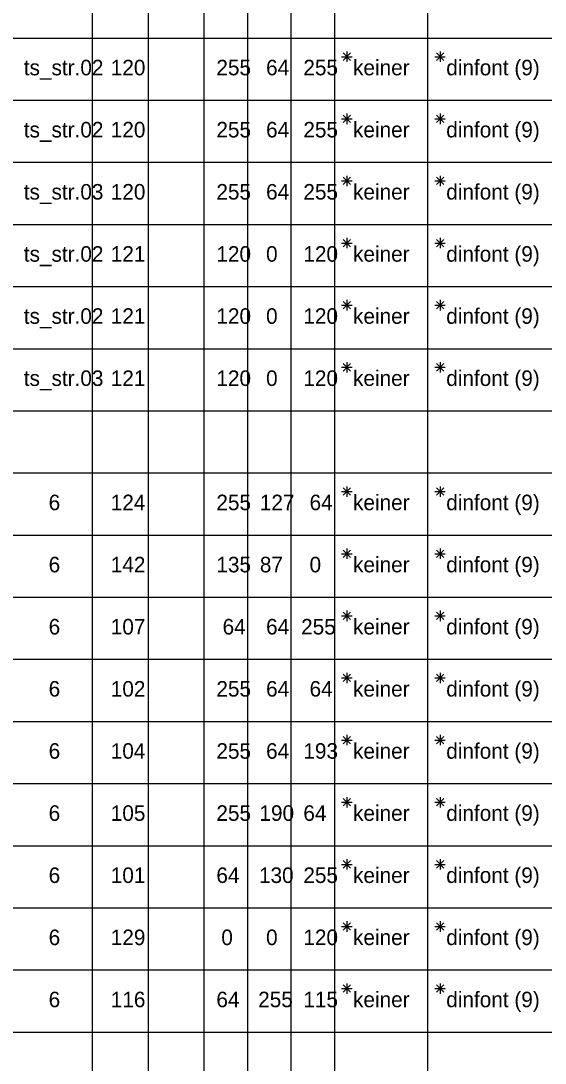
# Model space of a CAD drawing. Extents: x -14.5 to 23.8, y -56.3 to 8.
# Drawn here: x 11.73 to 15.95, y -23.75 to -15.36 of the extents above; entities that cross this region are included whole.
import ezdxf

# ---------------------------------------------------------------- set-up
doc = ezdxf.new("R2010")
doc.units = 0
doc.layers.add('Default', color=7, linetype='Continuous')

msp = doc.modelspace()

# ---------------------------------------------------------------- linework, layer by layer
at = {"layer": 'Default'}
for p, q in [((12.3, -0.35), (12.3, -44.5)), ((12.75, -0.35), (12.75, -44.5)), ((13.2, -0.35), (13.2, -44.5)), ((14.25, -0.35), (14.25, -48)), ((15, -0.35), (15, -48)), ((13.55, -0.75), (13.55, -44.5)), ((13.9, -0.75), (13.9, -44.5)), ((0, -15.5), (16, -15.5)), ((14.3081, -15.65), (14.3919, -15.65)), ((14.3203, -15.6203), (14.3797, -15.6797)), ((14.3797, -15.6203), (14.3203, -15.6797)), ((14.35, -15.6081), (14.35, -15.6919)), ((15.0581, -15.65), (15.1419, -15.65)), ((15.0703, -15.6203), (15.1297, -15.6797)), ((15.1297, -15.6203), (15.0703, -15.6797)), ((15.1, -15.6081), (15.1, -15.6919)), ((0, -16), (16, -16)), ((14.3081, -16.15), (14.3919, -16.15)), ((14.3203, -16.1203), (14.3797, -16.1797)), ((14.3797, -16.1203), (14.3203, -16.1797)), ((14.35, -16.1081), (14.35, -16.1919)), ((15.0581, -16.15), (15.1419, -16.15)), ((15.0703, -16.1203), (15.1297, -16.1797)), ((15.1297, -16.1203), (15.0703, -16.1797)), ((15.1, -16.1081), (15.1, -16.1919)), ((0, -16.5), (16, -16.5)), ((14.35, -16.6081), (14.35, -16.6919)), ((15.1, -16.6081), (15.1, -16.6919)), ((14.3081, -16.65), (14.3919, -16.65)), ((14.3203, -16.6203), (14.3797, -16.6797)), ((14.3797, -16.6203), (14.3203, -16.6797)), ((15.0581, -16.65), (15.1419, -16.65)), ((15.0703, -16.6203), (15.1297, -16.6797)), ((15.1297, -16.6203), (15.0703, -16.6797)), ((0, -17), (16, -17)), ((14.35, -17.1081), (14.35, -17.1919)), ((15.1, -17.1081), (15.1, -17.1919)), ((14.3081, -17.15), (14.3919, -17.15)), ((14.3203, -17.1203), (14.3797, -17.1797)), ((14.3797, -17.1203), (14.3203, -17.1797)), ((15.0581, -17.15), (15.1419, -17.15)), ((15.0703, -17.1203), (15.1297, -17.1797)), ((15.1297, -17.1203), (15.0703, -17.1797)), ((0, -17.5), (16, -17.5)), ((14.35, -17.6081), (14.35, -17.6919)), ((15.1, -17.6081), (15.1, -17.6919)), ((14.3081, -17.65), (14.3919, -17.65)), ((14.3203, -17.6203), (14.3797, -17.6797)), ((14.3797, -17.6203), (14.3203, -17.6797)), ((15.0581, -17.65), (15.1419, -17.65)), ((15.0703, -17.6203), (15.1297, -17.6797)), ((15.1297, -17.6203), (15.0703, -17.6797)), ((0, -18), (16, -18)), ((14.35, -18.1081), (14.35, -18.1919)), ((15.1, -18.1081), (15.1, -18.1919)), ((14.3081, -18.15), (14.3919, -18.15)), ((14.3203, -18.1203), (14.3797, -18.1797)), ((14.3797, -18.1203), (14.3203, -18.1797)), ((15.0581, -18.15), (15.1419, -18.15)), ((15.0703, -18.1203), (15.1297, -18.1797)), ((15.1297, -18.1203), (15.0703, -18.1797)), ((0, -18.5), (16, -18.5)), ((0, -19), (16, -19)), ((14.3203, -19.1203), (14.3797, -19.1797)), ((14.3797, -19.1203), (14.3203, -19.1797)), ((14.35, -19.1081), (14.35, -19.1919)), ((15.0703, -19.1203), (15.1297, -19.1797)), ((15.1297, -19.1203), (15.0703, -19.1797)), ((15.1, -19.1081), (15.1, -19.1919)), ((14.3081, -19.15), (14.3919, -19.15)), ((15.0581, -19.15), (15.1419, -19.15)), ((0, -19.5), (16, -19.5)), ((14.3203, -19.6203), (14.3797, -19.6797)), ((14.3797, -19.6203), (14.3203, -19.6797)), ((14.35, -19.6081), (14.35, -19.6919)), ((15.0703, -19.6203), (15.1297, -19.6797)), ((15.1297, -19.6203), (15.0703, -19.6797)), ((15.1, -19.6081), (15.1, -19.6919)), ((14.3081, -19.65), (14.3919, -19.65)), ((15.0581, -19.65), (15.1419, -19.65)), ((0, -20), (16, -20)), ((14.3203, -20.1203), (14.3797, -20.1797)), ((14.3797, -20.1203), (14.3203, -20.1797)), ((14.35, -20.1081), (14.35, -20.1919)), ((15.0703, -20.1203), (15.1297, -20.1797)), ((15.1297, -20.1203), (15.0703, -20.1797)), ((15.1, -20.1081), (15.1, -20.1919)), ((14.3081, -20.15), (14.3919, -20.15)), ((15.0581, -20.15), (15.1419, -20.15)), ((0, -20.5), (16, -20.5)), ((14.3203, -20.6203), (14.3797, -20.6797)), ((14.3797, -20.6203), (14.3203, -20.6797)), ((14.35, -20.6081), (14.35, -20.6919)), ((15.0703, -20.6203), (15.1297, -20.6797)), ((15.1297, -20.6203), (15.0703, -20.6797)), ((15.1, -20.6081), (15.1, -20.6919)), ((14.3081, -20.65), (14.3919, -20.65)), ((15.0581, -20.65), (15.1419, -20.65)), ((0, -21), (16, -21)), ((14.3203, -21.1203), (14.3797, -21.1797)), ((14.3797, -21.1203), (14.3203, -21.1797)), ((14.35, -21.1081), (14.35, -21.1919)), ((15.0703, -21.1203), (15.1297, -21.1797)), ((15.1297, -21.1203), (15.0703, -21.1797)), ((15.1, -21.1081), (15.1, -21.1919)), ((14.3081, -21.15), (14.3919, -21.15)), ((15.0581, -21.15), (15.1419, -21.15)), ((0, -21.5), (16, -21.5)), ((14.3203, -21.6203), (14.3797, -21.6797)), ((14.3797, -21.6203), (14.3203, -21.6797)), ((14.35, -21.6081), (14.35, -21.6919)), ((15.0703, -21.6203), (15.1297, -21.6797)), ((15.1297, -21.6203), (15.0703, -21.6797)), ((15.1, -21.6081), (15.1, -21.6919)), ((14.3081, -21.65), (14.3919, -21.65)), ((15.0581, -21.65), (15.1419, -21.65)), ((0, -22), (16, -22)), ((14.3203, -22.1203), (14.3797, -22.1797)), ((14.3797, -22.1203), (14.3203, -22.1797)), ((14.35, -22.1081), (14.35, -22.1919)), ((15.0703, -22.1203), (15.1297, -22.1797)), ((15.1297, -22.1203), (15.0703, -22.1797)), ((15.1, -22.1081), (15.1, -22.1919)), ((14.3081, -22.15), (14.3919, -22.15)), ((15.0581, -22.15), (15.1419, -22.15)), ((0, -22.5), (16, -22.5)), ((14.3203, -22.6203), (14.3797, -22.6797)), ((14.3797, -22.6203), (14.3203, -22.6797)), ((14.35, -22.6081), (14.35, -22.6919)), ((15.0703, -22.6203), (15.1297, -22.6797)), ((15.1297, -22.6203), (15.0703, -22.6797)), ((15.1, -22.6081), (15.1, -22.6919)), ((14.3081, -22.65), (14.3919, -22.65)), ((15.0581, -22.65), (15.1419, -22.65)), ((0, -23), (16, -23)), ((14.3081, -23.15), (14.3919, -23.15)), ((14.3203, -23.1203), (14.3797, -23.1797)), ((14.3797, -23.1203), (14.3203, -23.1797)), ((14.35, -23.1081), (14.35, -23.1919)), ((15.0581, -23.15), (15.1419, -23.15)), ((15.0703, -23.1203), (15.1297, -23.1797)), ((15.1297, -23.1203), (15.0703, -23.1797)), ((15.1, -23.1081), (15.1, -23.1919)), ((0, -23.5), (16, -23.5))]:
    msp.add_line(p, q, dxfattribs=at)

# ---------------------------------------------------------------- texts
for s, p in [('ts_str.02', (11.75, -15.8)), ('120', (12.45, -15.8)), ('255', (13.3, -15.8)), ('64', (13.7, -15.8)), ('255', (14, -15.8)), ('keiner', (14.4, -15.8)), ('dinfont (9)', (15.15, -15.8)), ('ts_str.02', (11.75, -16.3)), ('120', (12.45, -16.3)), ('255', (13.3, -16.3)), ('64', (13.7, -16.3)), ('255', (14, -16.3)), ('keiner', (14.4, -16.3)), ('dinfont (9)', (15.15, -16.3)), ('ts_str.03', (11.75, -16.8)), ('120', (12.45, -16.8)), ('255', (13.3, -16.8)), ('64', (13.7, -16.8)), ('255', (14, -16.8)), ('keiner', (14.4, -16.8)), ('dinfont (9)', (15.15, -16.8)), ('ts_str.02', (11.75, -17.3)), ('121', (12.45, -17.3)), ('120', (13.3, -17.3)), ('0', (13.7, -17.3)), ('120', (14, -17.3)), ('keiner', (14.4, -17.3)), ('dinfont (9)', (15.15, -17.3)), ('ts_str.02', (11.75, -17.8)), ('121', (12.45, -17.8)), ('120', (13.3, -17.8)), ('0', (13.7, -17.8)), ('120', (14, -17.8)), ('keiner', (14.4, -17.8)), ('dinfont (9)', (15.15, -17.8)), ('ts_str.03', (11.75, -18.3)), ('121', (12.45, -18.3)), ('120', (13.3, -18.3)), ('0', (13.7, -18.3)), ('120', (14, -18.3)), ('keiner', (14.4, -18.3)), ('dinfont (9)', (15.15, -18.3)), ('6', (11.95, -19.3)), ('124', (12.45, -19.3)), ('255', (13.3, -19.3)), ('127', (13.65, -19.3)), ('64', (14.05, -19.3)), ('keiner', (14.4, -19.3)), ('dinfont (9)', (15.15, -19.3)), ('6', (11.95, -19.8)), ('142', (12.45, -19.8)), ('135', (13.3, -19.8)), ('87', (13.65, -19.8)), ('0', (14.05, -19.8)), ('keiner', (14.4, -19.8)), ('dinfont (9)', (15.15, -19.8)), ('6', (11.95, -20.3)), ('107', (12.45, -20.3)), ('64', (13.35, -20.3)), ('64', (13.7, -20.3)), ('255', (13.9819, -20.3)), ('keiner', (14.4, -20.3)), ('dinfont (9)', (15.15, -20.3)), ('6', (11.95, -20.8)), ('102', (12.45, -20.8)), ('255', (13.3, -20.8)), ('64', (13.7, -20.8)), ('64', (14.05, -20.8)), ('keiner', (14.4, -20.8)), ('dinfont (9)', (15.15, -20.8)), ('6', (11.95, -21.3)), ('104', (12.45, -21.3)), ('255', (13.3, -21.3)), ('64', (13.7, -21.3)), ('193', (14, -21.3)), ('keiner', (14.4, -21.3)), ('dinfont (9)', (15.15, -21.3)), ('6', (11.95, -21.8)), ('105', (12.45, -21.8)), ('255', (13.3, -21.8)), ('190', (13.6465, -21.8)), ('64', (14, -21.8)), ('keiner', (14.4, -21.8)), ('dinfont (9)', (15.15, -21.8)), ('6', (11.95, -22.3)), ('101', (12.45, -22.3)), ('64', (13.3, -22.3)), ('130', (13.6429, -22.3)), ('255', (14, -22.3)), ('keiner', (14.4, -22.3)), ('dinfont (9)', (15.15, -22.3)), ('6', (11.95, -22.8)), ('129', (12.45, -22.8)), ('0', (13.3397, -22.8)), ('0', (13.7, -22.8)), ('120', (14, -22.8)), ('keiner', (14.4, -22.8)), ('dinfont (9)', (15.15, -22.8)), ('6', (11.95, -23.3)), ('116', (12.45, -23.3)), ('64', (13.3, -23.3)), ('255', (13.6363, -23.3)), ('115', (14, -23.3)), ('keiner', (14.4, -23.3)), ('dinfont (9)', (15.15, -23.3))]:
    msp.add_text(s, height=0.125, dxfattribs=at).set_placement(p)

doc.saveas('drawing.dxf')
